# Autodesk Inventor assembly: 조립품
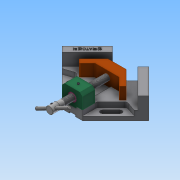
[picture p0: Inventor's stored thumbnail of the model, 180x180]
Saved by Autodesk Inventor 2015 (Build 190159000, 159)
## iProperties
Created: 2019-04
Part Number: 조립품
Document SubType Name: Assembly
Designer: SCD-A01
Author: SCD-A01
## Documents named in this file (11)
- C:\Users\SCD-A01\Desktop\490407V1008\490407V1008\조립품.iam
- C:\Users\SCD-A01\Desktop\490407V1008\본체.ipt
- C:\Users\SCD-A01\Desktop\490407V1008\490407V1008\리드스크류.ipt
- C:\Users\SCD-A01\Desktop\490407V1008\490407V1008\멈춤나사 M4x5.ipt
- C:\Users\SCD-A01\Desktop\490407V1008\490407V1008\멈춤나사 M4x10.ipt
- C:\Users\SCD-A01\Desktop\490407V1008\490407V1008\볼트 M4x16.ipt
- C:\Users\SCD-A01\Desktop\490407V1008\490407V1008\부시.ipt
- C:\Users\SCD-A01\Desktop\490407V1008\490407V1008\서포트.ipt
- C:\Users\SCD-A01\Desktop\490407V1008\490407V1008\조.ipt
- C:\Users\SCD-A01\Desktop\490407V1008\490407V1008\평행 핀 2.5x24.ipt
- C:\Users\SCD-A01\Desktop\490407V1008\490407V1008\핸들.ipt
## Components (1 placed, 1 different names)
1. 핸들:1
